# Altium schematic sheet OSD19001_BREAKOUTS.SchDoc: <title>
size B; CompanyName: Allied Component Works; Organization: Altium Limited; DocumentNumber: 3; Revision: X1; SheetNumber: 3; SheetTotal: 4; DrawingNumber: <drawing number>; SchematicTitle: OSD32MP1 BREAKOUT MODULE (BREAKOUTS)
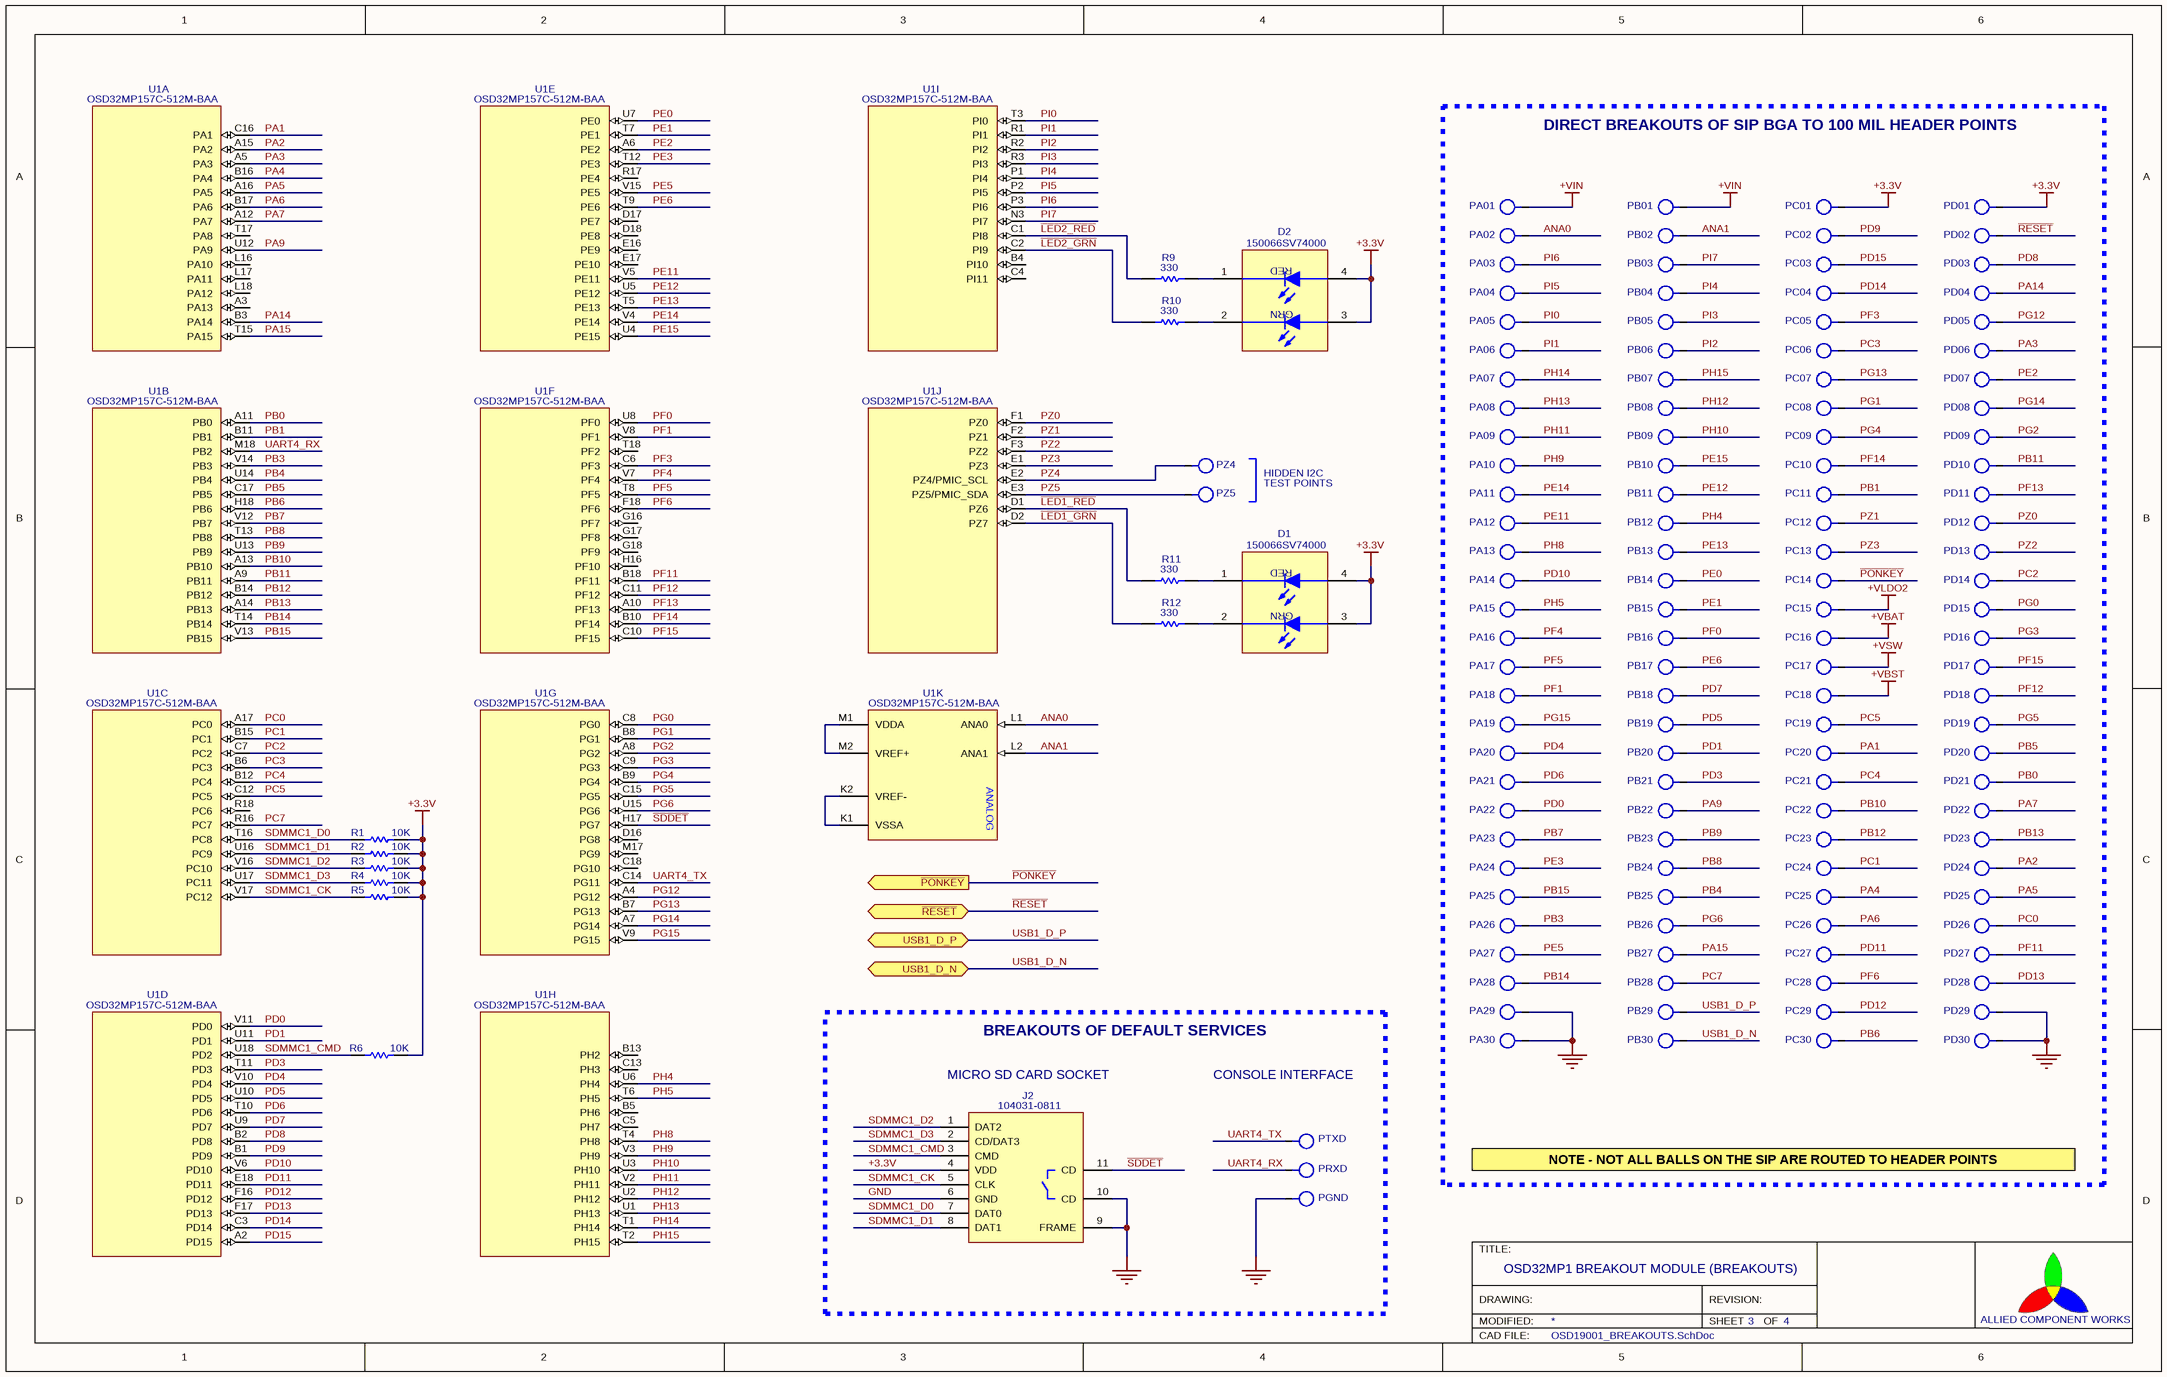
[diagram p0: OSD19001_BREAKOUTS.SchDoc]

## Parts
D1  150066SV74000  [WURTH_DUAL_0606]
D2  150066SV74000  [WURTH_DUAL_0606]
J2  104031-0811  [MOLEX_104031-0811]
PA01  TP  [LP_TESTPOINT_TH]  (value not drawn)
PA02  TP  [LP_TESTPOINT_TH]  (value not drawn)
PA03  TP  [LP_TESTPOINT_TH]  (value not drawn)
PA04  TP  [LP_TESTPOINT_TH]  (value not drawn)
PA05  TP  [LP_TESTPOINT_TH]  (value not drawn)
PA06  TP  [LP_TESTPOINT_TH]  (value not drawn)
PA07  TP  [LP_TESTPOINT_TH]  (value not drawn)
PA08  TP  [LP_TESTPOINT_TH]  (value not drawn)
PA09  TP  [LP_TESTPOINT_TH]  (value not drawn)
PA10  TP  [LP_TESTPOINT_TH]  (value not drawn)
PA11  TP  [LP_TESTPOINT_TH]  (value not drawn)
PA12  TP  [LP_TESTPOINT_TH]  (value not drawn)
PA13  TP  [LP_TESTPOINT_TH]  (value not drawn)
PA14  TP  [LP_TESTPOINT_TH]  (value not drawn)
PA15  TP  [LP_TESTPOINT_TH]  (value not drawn)
PA16  TP  [LP_TESTPOINT_TH]  (value not drawn)
PA17  TP  [LP_TESTPOINT_TH]  (value not drawn)
PA18  TP  [LP_TESTPOINT_TH]  (value not drawn)
PA19  TP  [LP_TESTPOINT_TH]  (value not drawn)
PA20  TP  [LP_TESTPOINT_TH]  (value not drawn)
PA21  TP  [LP_TESTPOINT_TH]  (value not drawn)
PA22  TP  [LP_TESTPOINT_TH]  (value not drawn)
PA23  TP  [LP_TESTPOINT_TH]  (value not drawn)
PA24  TP  [LP_TESTPOINT_TH]  (value not drawn)
PA25  TP  [LP_TESTPOINT_TH]  (value not drawn)
PA26  TP  [LP_TESTPOINT_TH]  (value not drawn)
PA27  TP  [LP_TESTPOINT_TH]  (value not drawn)
PA28  TP  [LP_TESTPOINT_TH]  (value not drawn)
PA29  TP  [LP_TESTPOINT_TH]  (value not drawn)
PA30  TP  [LP_TESTPOINT_TH]  (value not drawn)
PB01  TP  [LP_TESTPOINT_TH]  (value not drawn)
PB02  TP  [LP_TESTPOINT_TH]  (value not drawn)
PB03  TP  [LP_TESTPOINT_TH]  (value not drawn)
PB04  TP  [LP_TESTPOINT_TH]  (value not drawn)
PB05  TP  [LP_TESTPOINT_TH]  (value not drawn)
PB06  TP  [LP_TESTPOINT_TH]  (value not drawn)
PB07  TP  [LP_TESTPOINT_TH]  (value not drawn)
PB08  TP  [LP_TESTPOINT_TH]  (value not drawn)
PB09  TP  [LP_TESTPOINT_TH]  (value not drawn)
PB10  TP  [LP_TESTPOINT_TH]  (value not drawn)
PB11  TP  [LP_TESTPOINT_TH]  (value not drawn)
PB12  TP  [LP_TESTPOINT_TH]  (value not drawn)
PB13  TP  [LP_TESTPOINT_TH]  (value not drawn)
PB14  TP  [LP_TESTPOINT_TH]  (value not drawn)
PB15  TP  [LP_TESTPOINT_TH]  (value not drawn)
PB16  TP  [LP_TESTPOINT_TH]  (value not drawn)
PB17  TP  [LP_TESTPOINT_TH]  (value not drawn)
PB18  TP  [LP_TESTPOINT_TH]  (value not drawn)
PB19  TP  [LP_TESTPOINT_TH]  (value not drawn)
PB20  TP  [LP_TESTPOINT_TH]  (value not drawn)
PB21  TP  [LP_TESTPOINT_TH]  (value not drawn)
PB22  TP  [LP_TESTPOINT_TH]  (value not drawn)
PB23  TP  [LP_TESTPOINT_TH]  (value not drawn)
PB24  TP  [LP_TESTPOINT_TH]  (value not drawn)
PB25  TP  [LP_TESTPOINT_TH]  (value not drawn)
PB26  TP  [LP_TESTPOINT_TH]  (value not drawn)
PB27  TP  [LP_TESTPOINT_TH]  (value not drawn)
PB28  TP  [LP_TESTPOINT_TH]  (value not drawn)
PB29  TP  [LP_TESTPOINT_TH]  (value not drawn)
PB30  TP  [LP_TESTPOINT_TH]  (value not drawn)
PC01  TP  [LP_TESTPOINT_TH]  (value not drawn)
PC02  TP  [LP_TESTPOINT_TH]  (value not drawn)
PC03  TP  [LP_TESTPOINT_TH]  (value not drawn)
PC04  TP  [LP_TESTPOINT_TH]  (value not drawn)
PC05  TP  [LP_TESTPOINT_TH]  (value not drawn)
PC06  TP  [LP_TESTPOINT_TH]  (value not drawn)
PC07  TP  [LP_TESTPOINT_TH]  (value not drawn)
PC08  TP  [LP_TESTPOINT_TH]  (value not drawn)
PC09  TP  [LP_TESTPOINT_TH]  (value not drawn)
PC10  TP  [LP_TESTPOINT_TH]  (value not drawn)
PC11  TP  [LP_TESTPOINT_TH]  (value not drawn)
PC12  TP  [LP_TESTPOINT_TH]  (value not drawn)
PC13  TP  [LP_TESTPOINT_TH]  (value not drawn)
PC14  TP  [LP_TESTPOINT_TH]  (value not drawn)
PC15  TP  [LP_TESTPOINT_TH]  (value not drawn)
PC16  TP  [LP_TESTPOINT_TH]  (value not drawn)
PC17  TP  [LP_TESTPOINT_TH]  (value not drawn)
PC18  TP  [LP_TESTPOINT_TH]  (value not drawn)
PC19  TP  [LP_TESTPOINT_TH]  (value not drawn)
PC20  TP  [LP_TESTPOINT_TH]  (value not drawn)
PC21  TP  [LP_TESTPOINT_TH]  (value not drawn)
PC22  TP  [LP_TESTPOINT_TH]  (value not drawn)
PC23  TP  [LP_TESTPOINT_TH]  (value not drawn)
PC24  TP  [LP_TESTPOINT_TH]  (value not drawn)
PC25  TP  [LP_TESTPOINT_TH]  (value not drawn)
PC26  TP  [LP_TESTPOINT_TH]  (value not drawn)
PC27  TP  [LP_TESTPOINT_TH]  (value not drawn)
PC28  TP  [LP_TESTPOINT_TH]  (value not drawn)
PC29  TP  [LP_TESTPOINT_TH]  (value not drawn)
PC30  TP  [LP_TESTPOINT_TH]  (value not drawn)
PD01  TP  [LP_TESTPOINT_TH]  (value not drawn)
PD02  TP  [LP_TESTPOINT_TH]  (value not drawn)
PD03  TP  [LP_TESTPOINT_TH]  (value not drawn)
PD04  TP  [LP_TESTPOINT_TH]  (value not drawn)
PD05  TP  [LP_TESTPOINT_TH]  (value not drawn)
PD06  TP  [LP_TESTPOINT_TH]  (value not drawn)
PD07  TP  [LP_TESTPOINT_TH]  (value not drawn)
PD08  TP  [LP_TESTPOINT_TH]  (value not drawn)
PD09  TP  [LP_TESTPOINT_TH]  (value not drawn)
PD10  TP  [LP_TESTPOINT_TH]  (value not drawn)
PD11  TP  [LP_TESTPOINT_TH]  (value not drawn)
PD12  TP  [LP_TESTPOINT_TH]  (value not drawn)
PD13  TP  [LP_TESTPOINT_TH]  (value not drawn)
PD14  TP  [LP_TESTPOINT_TH]  (value not drawn)
PD15  TP  [LP_TESTPOINT_TH]  (value not drawn)
PD16  TP  [LP_TESTPOINT_TH]  (value not drawn)
PD17  TP  [LP_TESTPOINT_TH]  (value not drawn)
PD18  TP  [LP_TESTPOINT_TH]  (value not drawn)
PD19  TP  [LP_TESTPOINT_TH]  (value not drawn)
PD20  TP  [LP_TESTPOINT_TH]  (value not drawn)
PD21  TP  [LP_TESTPOINT_TH]  (value not drawn)
PD22  TP  [LP_TESTPOINT_TH]  (value not drawn)
PD23  TP  [LP_TESTPOINT_TH]  (value not drawn)
PD24  TP  [LP_TESTPOINT_TH]  (value not drawn)
PD25  TP  [LP_TESTPOINT_TH]  (value not drawn)
PD26  TP  [LP_TESTPOINT_TH]  (value not drawn)
PD27  TP  [LP_TESTPOINT_TH]  (value not drawn)
PD28  TP  [LP_TESTPOINT_TH]  (value not drawn)
PD29  TP  [LP_TESTPOINT_TH]  (value not drawn)
PD30  TP  [LP_TESTPOINT_TH]  (value not drawn)
PGND  TP  [LP_TESTPOINT_TH]  (value not drawn)
PRXD  TP  [LP_TESTPOINT_TH]  (value not drawn)
PTXD  TP  [LP_TESTPOINT_TH]  (value not drawn)
PZ4  TP  [LP_TESTPOINT_SMT]  (value not drawn)
PZ5  TP  [LP_TESTPOINT_SMT]  (value not drawn)
R1  10K  [LP_0402_LOW]
R2  10K  [LP_0402_LOW]
R3  10K  [LP_0402_LOW]
R4  10K  [LP_0402_LOW]
R5  10K  [LP_0402_LOW]
R6  10K  [LP_0402_LOW]
R9  330  [LP_0402_LOW]
R10  330  [LP_0402_LOW]
R11  330  [LP_0402_LOW]
R12  330  [LP_0402_LOW]
U1  OSD32MP157C-512M-BAA  [BGA_OCTAVO_SIP_OSD32MP157C]  (parts A,B,C,D,E,F,G,H,I,J,K of 17)

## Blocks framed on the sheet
DIRECT BREAKOUTS OF SIP BGA TO 100 MIL HEADER POINTS: PA01 PA02 PA03 PA04 PA05 PA06 PA07 PA08 PA09-PA30 PB01 PB02 PB03 PB04 PB05 PB06 PB07 PB08 PB09-PB30 PC01 PC02 PC03 PC04 PC05 PC06 PC07 PC08 PC09-PC30 PD01 PD02 PD03 PD04 PD05 PD06 PD07 PD08 PD09-PD30
BREAKOUTS OF DEFAULT SERVICES: J2 PGND PRXD PTXD

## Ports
USB1_D_N (bidir), USB1_D_P (bidir), ~{PONKEY} (out), ~{RESET} (bidir)

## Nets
+3.3V: D1.3(A) D1.4(A) D2.3(A) D2.4(A) J2.4(VDD) PC01.1 PD01.1 R1.2 R2.2 R3.2 R4.2 R5.2 R6.2
+VBAT: PC16.1
+VBST: PC18.1
+VIN: PA01.1 PB01.1
+VLDO2: PC15.1
+VSW: PC17.1
GND: J2.6(GND) J2.9(FRAME) J2.10(CD) PA29.1 PA30.1 PD29.1 PD30.1 PGND.1
~{LED1_GRN}: R12.1 U1.D2(PZ7)
~{LED1_RED}: R11.1 U1.D1(PZ6)
~{LED2_GRN}: R10.1 U1.C2(PI9)
~{LED2_RED}: R9.1 U1.C1(PI8)
~{PONKEY}: PC14.1 ; port ~{PONKEY}
~{RESET}: PD02.1 ; port ~{RESET}
~{SDDET}: J2.11(CD) U1.H17(PG7)
ANA0: PA02.1 U1.L1(ANA0)
ANA1: PB02.1 U1.L2(ANA1)
PA1: PC20.1 U1.C16(PA1)
PA2: PD24.1 U1.A15(PA2)
PA3: PD06.1 U1.A5(PA3)
PA4: PC25.1 U1.B16(PA4)
PA5: PD25.1 U1.A16(PA5)
PA6: PC26.1 U1.B17(PA6)
PA7: PD22.1 U1.A12(PA7)
PA9: PB22.1 U1.U12(PA9)
PA14: PD04.1 U1.B3(PA14)
PA15: PB27.1 U1.T15(PA15)
PB0: PD21.1 U1.A11(PB0)
PB1: PC11.1 U1.B11(PB1)
PB3: PA26.1 U1.V14(PB3)
PB4: PB25.1 U1.U14(PB4)
PB5: PD20.1 U1.C17(PB5)
PB6: PC30.1 U1.H18(PB6)
PB7: PA23.1 U1.V12(PB7)
PB8: PB24.1 U1.T13(PB8)
PB9: PB23.1 U1.U13(PB9)
PB10: PC22.1 U1.A13(PB10)
PB11: PD10.1 U1.A9(PB11)
PB12: PC23.1 U1.B14(PB12)
PB13: PD23.1 U1.A14(PB13)
PB14: PA28.1 U1.T14(PB14)
PB15: PA25.1 U1.V13(PB15)
PC0: PD26.1 U1.A17(PC0)
PC1: PC24.1 U1.B15(PC1)
PC2: PD14.1 U1.C7(PC2)
PC3: PC06.1 U1.B6(PC3)
PC4: PC21.1 U1.B12(PC4)
PC5: PC19.1 U1.C12(PC5)
PC7: PB28.1 U1.R16(PC7)
PD0: PA22.1 U1.V11(PD0)
PD1: PB20.1 U1.U11(PD1)
PD3: PB21.1 U1.T11(PD3)
PD4: PA20.1 U1.V10(PD4)
PD5: PB19.1 U1.U10(PD5)
PD6: PA21.1 U1.T10(PD6)
PD7: PB18.1 U1.U9(PD7)
PD8: PD03.1 U1.B2(PD8)
PD9: PC02.1 U1.B1(PD9)
PD10: PA14.1 U1.V6(PD10)
PD11: PC27.1 U1.E18(PD11)
PD12: PC29.1 U1.F16(PD12)
PD13: PD28.1 U1.F17(PD13)
PD14: PC04.1 U1.C3(PD14)
PD15: PC03.1 U1.A2(PD15)
PE0: PB14.1 U1.U7(PE0)
PE1: PB15.1 U1.T7(PE1)
PE2: PD07.1 U1.A6(PE2)
PE3: PA24.1 U1.T12(PE3)
PE5: PA27.1 U1.V15(PE5)
PE6: PB17.1 U1.T9(PE6)
PE11: PA12.1 U1.V5(PE11)
PE12: PB11.1 U1.U5(PE12)
PE13: PB13.1 U1.T5(PE13)
PE14: PA11.1 U1.V4(PE14)
PE15: PB10.1 U1.U4(PE15)
PF0: PB16.1 U1.U8(PF0)
PF1: PA18.1 U1.V8(PF1)
PF3: PC05.1 U1.C6(PF3)
PF4: PA16.1 U1.V7(PF4)
PF5: PA17.1 U1.T8(PF5)
PF6: PC28.1 U1.F18(PF6)
PF11: PD27.1 U1.B18(PF11)
PF12: PD18.1 U1.C11(PF12)
PF13: PD11.1 U1.A10(PF13)
PF14: PC10.1 U1.B10(PF14)
PF15: PD17.1 U1.C10(PF15)
PG0: PD15.1 U1.C8(PG0)
PG1: PC08.1 U1.B8(PG1)
PG2: PD09.1 U1.A8(PG2)
PG3: PD16.1 U1.C9(PG3)
PG4: PC09.1 U1.B9(PG4)
PG5: PD19.1 U1.C15(PG5)
PG6: PB26.1 U1.U15(PG6)
PG12: PD05.1 U1.A4(PG12)
PG13: PC07.1 U1.B7(PG13)
PG14: PD08.1 U1.A7(PG14)
PG15: PA19.1 U1.V9(PG15)
PH4: PB12.1 U1.U6(PH4)
PH5: PA15.1 U1.T6(PH5)
PH8: PA13.1 U1.T4(PH8)
PH9: PA10.1 U1.V3(PH9)
PH10: PB09.1 U1.U3(PH10)
PH11: PA09.1 U1.V2(PH11)
PH12: PB08.1 U1.U2(PH12)
PH13: PA08.1 U1.U1(PH13)
PH14: PA07.1 U1.T1(PH14)
PH15: PB07.1 U1.T2(PH15)
PI0: PA05.1 U1.T3(PI0)
PI1: PA06.1 U1.R1(PI1)
PI2: PB06.1 U1.R2(PI2)
PI3: PB05.1 U1.R3(PI3)
PI4: PB04.1 U1.P1(PI4)
PI5: PA04.1 U1.P2(PI5)
PI6: PA03.1 U1.P3(PI6)
PI7: PB03.1 U1.N3(PI7)
PZ0: PD12.1 U1.F1(PZ0)
PZ1: PC12.1 U1.F2(PZ1)
PZ2: PD13.1 U1.F3(PZ2)
PZ3: PC13.1 U1.E1(PZ3)
PZ4: PZ4.1 U1.E2(PZ4/PMIC_SCL)
PZ5: PZ5.1 U1.E3(PZ5/PMIC_SDA)
SDMMC1_CK: J2.5(CLK) R5.1 U1.V17(PC12)
SDMMC1_CMD: J2.3(CMD) R6.1 U1.U18(PD2)
SDMMC1_D0: J2.7(DAT0) R1.1 U1.T16(PC8)
SDMMC1_D1: J2.8(DAT1) R2.1 U1.U16(PC9)
SDMMC1_D2: J2.1(DAT2) R3.1 U1.V16(PC10)
SDMMC1_D3: J2.2(CD/DAT3) R4.1 U1.U17(PC11)
UART4_RX: PRXD.1 U1.M18(PB2)
UART4_TX: PTXD.1 U1.C14(PG11)
USB1_D_N: PB30.1 ; port USB1_D_N
USB1_D_P: PB29.1 ; port USB1_D_P
NetD1_1: D1.1(K) R11.2
NetD1_2: D1.2(K) R12.2
NetD2_1: D2.1(K) R9.2
NetD2_2: D2.2(K) R10.2
NetU1_K1: U1.K1(VSSA) U1.K2(VREF-)
NetU1_M1: U1.M1(VDDA) U1.M2(VREF+)

Not connected (* = marked no-connect by the designer): U1 A3(PA13) B4(PI10) B5(PH6) B13(PH2) C4(PI11) C5(PH7) C13(PH3) C18(PG10) D16(PG8) D17(PE7) D18(PE8) E16(PE9) E17(PE10) G16(PF7) G17(PF8) G18(PF9) H16(PF10) L16(PA10) L17(PA11) L18(PA12) M17(PG9) R17(PE4) R18(PC6) T17(PA8) T18(PF2)

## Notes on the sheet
- HIDDEN I2C
- TEST POINTS
- (near J2) MICRO SD CARD SOCKET
- CONSOLE INTERFACE
- NOTE - NOT ALL BALLS ON THE SIP ARE ROUTED TO HEADER POINTS

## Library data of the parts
D1 D2 = LED_DUAL_0606_WURTH: LED, Dual, 4-Wire, SMT
J2 = SD_CARD_SW: Micro SD Connector, With CD Switch
PA01 PA02 PA03 PA04 PA05 PA06 PA07 PA08 PA09-PA30 PB01 PB02 PB03 PB04 PB05 PB06 PB07 PB08 PB09-PB30 PC01 PC02 PC03 PC04 PC05 PC06 PC07 PC08 PC09-PC30 PD01 PD02 PD03 PD04 PD05 PD06 PD07 PD08 PD09-PD30 PGND PRXD PTXD PZ4 PZ5 = TEST_POINT
R1-R6 R9-R12 = RESISTOR: Tolerance: 5%; Power: 0.1W; Voltage: 50V
U1 = OSD32MP157C: Octavo ST Processor SIP; Manufacturer: Octavo Systems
